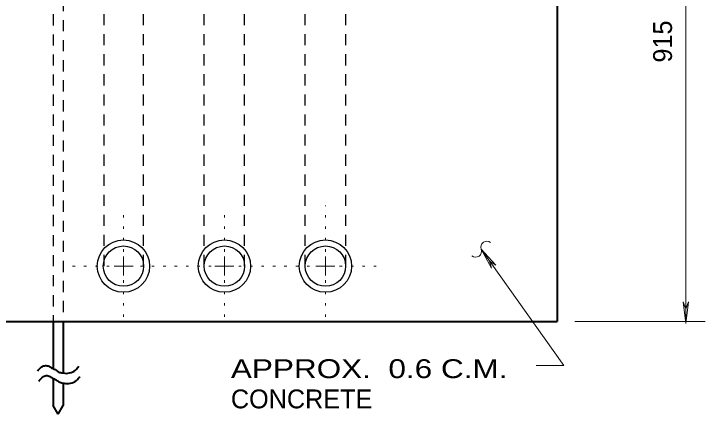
# Model space of a CAD drawing. Extents: x 312583 to 312854, y 144419 to 144597.
# Drawn here: x 312632.33 to 312660.21, y 144440.26 to 144456.42 of the extents above; entities that cross this region are included whole.
import ezdxf

# ---------------------------------------------------------------- set-up
doc = ezdxf.new("R2010")
doc.units = 0
doc.header["$LTSCALE"] = 0.3
doc.linetypes.add('DOTTED', pattern=[1.5, 0.3, -1.2])
doc.linetypes.add('SHORT_DASHED', pattern=[2.7, 1.5, -1.2])
doc.layers.add('1', color=7, linetype='Continuous', lineweight=25)
doc.layers.add('2', color=7, linetype='Continuous', lineweight=13)

msp = doc.modelspace()

# ---------------------------------------------------------------- linework, layer by layer
at = {"layer": '1', "lineweight": 40}
for p, q in [((312654.237, 144466.3672), (312654.237, 144444.0035)), ((312627.4036, 144444.0035), (312654.237, 144444.0035)), ((312633.9126, 144444.0035), (312633.9126, 144442.1175)), ((312634.3113, 144444.0035), (312634.3113, 144441.9259)), ((312633.9126, 144441.7035), (312633.9126, 144440.6149)), ((312634.3113, 144441.5195), (312634.3113, 144440.6149)), ((312634.112, 144440.2622), (312633.9126, 144440.6149)), ((312634.112, 144440.2622), (312634.3113, 144440.6149))]:
    msp.add_line(p, q, dxfattribs=at)
at = {"layer": '1', "linetype": 'SHORT_DASHED'}
for p, q in [((312633.9126, 144459.6435), (312633.9126, 144444.0035)), ((312634.3113, 144458.6009), (312634.3113, 144444.0035)), ((312635.9673, 144446.2422), (312635.9673, 144457.5812)), ((312637.562, 144446.2422), (312637.562, 144457.5812)), ((312640.0076, 144446.2422), (312640.0076, 144457.5812)), ((312641.633, 144446.2422), (312641.633, 144457.5812)), ((312644.0786, 144446.2422), (312644.0786, 144457.5812)), ((312645.7116, 144446.2422), (312645.7116, 144457.5812))]:
    msp.add_line(p, q, dxfattribs=at)
at = {"layer": '1'}
for centre, radius in [((312636.7474, 144446.239), 1.0542), ((312640.8203, 144446.239), 1.0542), ((312644.8932, 144446.239), 1.0542), ((312636.7474, 144446.239), 0.8146), ((312640.8203, 144446.239), 0.8146), ((312644.8932, 144446.239), 0.8146)]:
    msp.add_circle(centre, radius, dxfattribs=at)
at = {"layer": '1', "lineweight": 40}
for points in [[(312633.2916, 144442.0025), (312633.445, 144442.1712), (312633.5983, 144442.2249), (312633.744, 144442.1942), (312633.8743, 144442.1175), (312634.0276, 144442.0409), (312634.1426, 144441.9642), (312634.3113, 144441.9259), (312634.4416, 144441.9105), (312634.572, 144441.9259), (312634.8173, 144442.0409), (312634.9476, 144442.1942)], [(312633.33, 144441.5885), (312633.4833, 144441.7572), (312633.629, 144441.8185), (312633.7823, 144441.7802), (312633.9126, 144441.7035), (312634.066, 144441.6269), (312634.181, 144441.5502), (312634.3496, 144441.5119), (312634.48, 144441.4965), (312634.6103, 144441.5119), (312634.8556, 144441.6269), (312634.986, 144441.7802)]]:
    msp.add_spline(points, degree=3, dxfattribs=at)
at = {"layer": '2'}
for p, q in [((312659.4297, 144443.9287), (312659.4297, 144466.9287)), ((312651.178, 144446.9245), (312651.592, 144446.1502)), ((312651.178, 144446.9245), (312651.7683, 144446.2729)), ((312636.7493, 144446.2422), (312636.7493, 144446.6255)), ((312640.8203, 144446.2422), (312640.8203, 144446.6255)), ((312644.8913, 144446.2422), (312644.8913, 144446.6255)), ((312651.592, 144446.1502), (312651.5153, 144446.4415)), ((312651.7683, 144446.2729), (312651.5153, 144446.4415)), ((312636.7493, 144446.2422), (312636.366, 144446.2422)), ((312636.7493, 144446.2422), (312637.1326, 144446.2422)), ((312636.7493, 144446.2422), (312636.7493, 144445.8589)), ((312640.8203, 144446.2422), (312640.437, 144446.2422)), ((312640.8203, 144446.2422), (312641.2036, 144446.2422)), ((312640.8203, 144446.2422), (312640.8203, 144445.8589)), ((312644.8913, 144446.2422), (312644.508, 144446.2422)), ((312644.8913, 144446.2422), (312645.2746, 144446.2422)), ((312644.8913, 144446.2422), (312644.8913, 144445.8589)), ((312659.3223, 144444.7951), (312659.4297, 144444.5191)), ((312659.4297, 144443.9287), (312659.3223, 144444.7951)), ((312659.537, 144444.7951), (312659.4297, 144444.5191)), ((312659.4297, 144443.9287), (312659.537, 144444.7951)), ((312654.95, 144444.0035), (312660.2092, 144444.0035))]:
    msp.add_line(p, q, dxfattribs=at)
at = {"layer": '2', "linetype": 'DOTTED'}
for p, q in [((312636.7493, 144446.8172), (312636.7493, 144448.5729)), ((312640.8203, 144446.8172), (312640.8203, 144448.6189)), ((312644.8913, 144446.8172), (312644.8913, 144448.6802)), ((312636.1743, 144446.2422), (312634.3573, 144446.2422)), ((312640.2913, 144446.2422), (312637.2706, 144446.2422)), ((312641.3953, 144446.2422), (312644.3546, 144446.2422)), ((312645.4663, 144446.2422), (312647.1223, 144446.2422)), ((312636.7493, 144445.6672), (312636.7493, 144444.0495)), ((312640.8203, 144445.6672), (312640.8203, 144444.0112)), ((312644.8913, 144445.6672), (312644.8913, 144444.0879))]:
    msp.add_line(p, q, dxfattribs=at)
at = {"layer": '2'}
msp.add_lwpolyline([(312653.3936, 144442.2249), (312654.513, 144442.2249), (312651.178, 144446.9245)], dxfattribs=at)
for centre, start, end in [((312651.4006, 144447.0041), 50.36848, 200.36848), ((312650.9515, 144446.8373), 230.36848, 20.36848)]:
    msp.add_arc(centre, 0.2395, start, end, dxfattribs=at)

# ---------------------------------------------------------------- texts
msp.add_text('915', height=0.76, rotation=90, dxfattribs=at).set_placement((312658.8705, 144454.4547))
at = {"layer": '2', "width": 1.25}
msp.add_text('APPROX.  0.6 C.M.', height=0.76, dxfattribs=at).set_placement((312641.0805, 144441.7188))
at = {"layer": '2'}
msp.add_text('CONCRETE', height=0.76, dxfattribs=at).set_placement((312641.0805, 144440.4988))

doc.saveas('drawing.dxf')
